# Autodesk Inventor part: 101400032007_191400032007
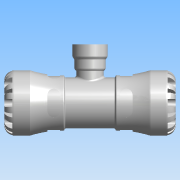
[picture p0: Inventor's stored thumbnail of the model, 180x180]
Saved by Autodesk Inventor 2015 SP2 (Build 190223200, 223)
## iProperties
Created: 2016-12
Part Number: 101400032007_191400032007
Material: PVC-Piping
Description: PLASSON TEE WITH THREADED FEMALE OFFTAKE 32X3/4" SERIES 1
Document SubType Name: Modeling
Designer: KIM
Mass: 664.223 g
Surface Area: 733.008 cm^2
Volume: 474.445 cm^3
Density: 1.4 g/cm^3
Appearance: Smooth - White
Author: KIM
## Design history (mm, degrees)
derived "1014.ipt"
feature "Solid1::1014.ipt"
tag "TaggingFeature1"
body "Solid1"
other parameters: "d1" = 22.68, "d2" = 32, "d4" = 58, "d8" = 49.3, "d13" = 7.2, "d14" = 7.2, "d15" = 0, "d17" = 360 deg, "d19" = 8 deg, "d20" = 0.64, "d21" = 0.64, "d22" = 8 deg, "d24" = 0, "d26" = 360 deg, "d33" = 5.8, "d43" = 45.24, "d51" = 0.58, "d54" = 11.2, "d55" = 7.04, "d57" = 14.112, "d58" = 0, "d74" = 0, "d77" = 2.66667, "d78" = 54, "d79" = 45.24, "d80" = 152, "d82" = 0.64, "d115" = 360 deg, "d139" = 7.2, "d140" = 0, "d142" = 360 deg, "d207" = 90 deg, "d228" = 9.52, "d247" = 1.16, "d248" = 3.24, "d266" = 0, "d268" = 24.117, "d270" = 3.61755, "d271" = 6, "d274" = 1.80878, "d275" = 52, "d276" = 2.4117, "d277" = 2.4117, "d278" = 2.4117, "d279" = 2.4117, "d281" = 0, "d282" = 18, "d_" = 32, "E_" = 58, "l_" = 54, "A_" = 52, "H_" = 152, "Rp_" = 24.117, "l_2" = 18, "d9" = 9, "d11" = 58
